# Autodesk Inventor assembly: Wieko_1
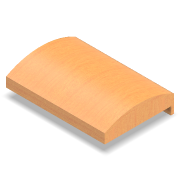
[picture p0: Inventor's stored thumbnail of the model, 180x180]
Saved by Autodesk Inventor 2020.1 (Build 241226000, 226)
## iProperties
Created: 2005-09
Part Number: Wieko_1
Document SubType Name: Assembly
Designer: F.Stasiak
Manager: www.cadconsulting.pl
Company: Fabian Stasiak CAD Consulting
Author: F.Stasiak
Subject: Zbiór ćwiczeń. Autodesk Inventor 2020. Kurs podstawowy
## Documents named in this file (3)
- C:\2020_Kurs_podstawowy\R6 Zespoły\Wiązania\Skrzynia I\Wieko_1.iam
- C:\2020_Kurs_podstawowy\R6 Zespoły\Wiązania\Skrzynia I\Bok wieka.ipt
- C:\2020_Kurs_podstawowy\R6 Zespoły\Wiązania\Skrzynia I\Wierzch wieka.ipt
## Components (3 placed, 2 different names)
1. Wierzch wieka:1 — Zestawiające:1, Zestawiające:2, Równoległe:1, Zestawiające:3, Zestawiające:4, Równoległe:2
2. Bok wieka:1 — Zestawiające:1, Zestawiające:2, Równoległe:1
3. Bok wieka:2 — Zestawiające:3, Zestawiające:4, Równoległe:2
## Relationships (6: Mate 4, Flush 2)
- Zestawiające:1 [Mate]: Wierzch wieka:1 ↔ Bok wieka:1
- Zestawiające:2 [Mate]: Wierzch wieka:1 ↔ Bok wieka:1
- Równoległe:1 [Flush]: Wierzch wieka:1 ↔ Bok wieka:1
- Zestawiające:3 [Mate]: Wierzch wieka:1 ↔ Bok wieka:2
- Zestawiające:4 [Mate]: Wierzch wieka:1 ↔ Bok wieka:2
- Równoległe:2 [Flush]: Wierzch wieka:1 ↔ Bok wieka:2
